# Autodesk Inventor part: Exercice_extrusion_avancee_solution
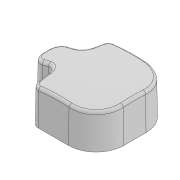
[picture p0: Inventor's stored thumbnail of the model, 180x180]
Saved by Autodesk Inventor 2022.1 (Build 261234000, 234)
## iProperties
Created: 2019-12
Part Number: Exercice_extrusion_avancee_solution
Material: Générique
Document SubType Name: Modeling
Designer: Fabian
Density: 1 g/cm^3
Appearance: Par défaut
Mass: 120.641 g
Surface Area: 860.643 cm^2
Volume: 120.641 cm^3
Author: Fabian
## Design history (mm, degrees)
sketch "Esquisse1"
  geometry: L1 (0, 70)-(0, -66.117); L2 (90, 0)-(-70, 0); L3 (90, 14.325)-(90, 0); L4 (-70, 45)-(-70, 0); L5 (44.578, 70)-(-45, 70); L6 (86.745, 24.649)-(60.961, 61.472); L7 (83, 0)-(83, 5); L8 (65, 23)-(55, 23); L9 (43, 35)-(43, 51); L10 (31, 63)-(-18, 63); L11 (-63, 18)-(-63, 0); L12 (-63, -18)-(-63, 0); L13 (0, -70)-(0, 66.117); L14 (-70, -45)-(-70, 0); L15 (31, -63)-(-18, -63); L16 (44.578, -70)-(-45, -70); L17 (43, -35)-(43, -51); L18 (90, -14.325)-(90, 0); L19 (86.745, -24.649)-(60.961, -61.472); L20 (83, 0)-(83, -5); L21 (65, -23)-(55, -23); C1 r 4 at (-60, 60); C2 r 6 at (55, 35); C3 r 4 at (-60, -60); C4 r 6 at (55, -35); A1 r 15 centre (-60, 60) between (-51, 72) and (-72, 51); A2 r 12 centre (55, 35) between (43, 35) and (55, 23); A3 r 12 centre (31, 51) between (43, 51) and (31, 63); A4 r 18 centre (72, 14.325) between (90, 14.325) and (86.745, 24.649); A5 r 20 centre (44.578, 50) between (60.961, 61.472) and (44.578, 70); A6 r 10 centre (-45, 80) between (-51, 72) and (-45, 70); A7 r 10 centre (-80, 45) between (-70, 45) and (-72, 51); A8 r 18 centre (65, 5) between (83, 5) and (65, 23); A9 r 45 centre (-18, 18) between (-18, 63) and (-63, 18); A10 r 45 centre (-18, -18) between (-63, -18) and (-18, -63); A11 r 12 centre (31, -51) between (31, -63) and (43, -51); A12 r 10 centre (-45, -80) between (-45, -70) and (-51, -72); A13 r 15 centre (-60, -60) between (-72, -51) and (-51, -72); A14 r 10 centre (-80, -45) between (-72, -51) and (-70, -45); A15 r 12 centre (55, -35) between (55, -23) and (43, -35); A16 r 20 centre (44.578, -50) between (44.578, -70) and (60.961, -61.472); A17 r 18 centre (65, -5) between (65, -23) and (83, -5); A18 r 18 centre (72, -14.325) between (86.745, -24.649) and (90, -14.325); 7 further points
  constraints: 44 end point, 40 point on circle, 32 symmetric about line, 22 centre point, 16 tangent, 14 point on line, 5 perpendicular, 4 coincident, 3 vertical, 2 horizontal, 11 other
  dimensions: "d2" = 70 distance between parallel lines of L4 L1; "d3" = 90 distance between parallel lines of L3 L1; "d5" = 30 diameter of A1; "d6" = 140 diameter of L5 L2; "d7" = 20 distance of point (90, 20) L2.start; "d8" = 35 deg angle of L3 L6; "d9" = 120 diameter of A1.centre L2; "d11" = 60 distance from line of A1.centre L1; "d12" = 8 diameter of C1; "d13" = 70 diameter of C2.centre L2; "d14" = 55 distance from line of C2.centre L1; "d15" = 12 diameter of C2; "d16" = 83 distance between parallel lines of L7 L1; "d17" = 63 distance between parallel lines of L11 L1; "d18" = 46 diameter of L8 L2 (derived); "d19" = 126 diameter of L10 L2; "d21" = 12 radius of A2; "d22" = 43 distance between parallel lines of L9 L1 (derived); "d23" = 12 radius of A3 (derived); "d24" = 18 radius of A4 (derived); "d25" = 20 radius of A5; "d26" = 10 radius of A6; "d27" = 10 radius of A7; "d28" = 18 radius of A8; "d29" = 45 radius of A9
extrude "Extrusion1" new body sketch "Esquisse1" distance "d30" = 65; taper "d31" = -1 deg
sketch "Esquisse2"
  geometry: L1 (-81.865, 65)-(61.865, 65); L2 (0, -455)-(0, 65); L3 (18, 65)-(-31, 65) reference; L4 (-55, 65)-(-65, 65) reference; A1 r 260 centre (0, -195) between (0, -455) and (0, 65); 1 further point
  constraints: 4 end point, 2 point on circle, 1 centre point, 1 collinear, 1 point on line, 1 tangent, 1 vertical, 1 vertical alignment
  dimensions: "d32" = 520 diameter of A1
revolve "Révolution1" sketch "Esquisse2" stored, may be unused: angle "d33" = 90 deg
fillet "Congé1" dims "d36" = 5
feature "Coque1" dims "d37" = 3
sketch "Esquisse3"
  geometry: L1 (-80, -5)-(-80, 5) reference; L2 (-65, 20)-(-55, 20) reference; L3 (-40, 35)-(-40, 51) reference; L4 (-31, 60)-(18, 60) reference; L5 (60, 18)-(60, -18) reference; L6 (18, -60)-(-31, -60) reference; L7 (-40, -51)-(-40, -35) reference; L8 (-55, -20)-(-65, -20) reference; L9 (-31, 63)-(18, 63) reference; L10 (-43, 35)-(-43, 51) reference; L11 (-65, 23)-(-55, 23) reference; L12 (-83, -5)-(-83, 5) reference; L13 (-55, -23)-(-65, -23) reference; L14 (-43, -51)-(-43, -35) reference; L15 (18, -63)-(-31, -63) reference; L16 (63, 18)-(63, -18) reference; L17 (18, 55)-(-31, 55); L18 (-35, 51)-(-35, 35); L19 (-55, 15)-(-65, 15); L20 (-75, 5)-(-75, -5); L21 (-65, -15)-(-55, -15); L22 (-35, -35)-(-35, -51); L23 (-31, -55)-(18, -55); L24 (55, -18)-(55, 18); L25 (-31, 56.5)-(18, 56.5); L26 (56.5, 18)-(56.5, -18); L27 (18, -56.5)-(-31, -56.5); L28 (-36.5, -51)-(-36.5, -35); L29 (-55, -16.5)-(-65, -16.5); L30 (-76.5, -5)-(-76.5, 5); L31 (-65, 16.5)-(-55, 16.5); L32 (-36.5, 35)-(-36.5, 51); A1 r 15 centre (-65, -5) between (-80, -5) and (-65, -20) reference; A2 r 15 centre (-65, 5) between (-65, 20) and (-80, 5) reference; A3 r 15 centre (-55, 35) between (-55, 20) and (-40, 35) reference; A4 r 9 centre (-31, 51) between (-31, 60) and (-40, 51) reference; A5 r 42 centre (18, 18) between (60, 18) and (18, 60) reference; A6 r 42 centre (18, -18) between (18, -60) and (60, -18) reference; A7 r 9 centre (-31, -51) between (-40, -51) and (-31, -60) reference; A8 r 15 centre (-55, -35) between (-40, -35) and (-55, -20) reference; A9 r 12 centre (-31, 51) between (-31, 63) and (-43, 51) reference; A10 r 12 centre (-55, 35) between (-55, 23) and (-43, 35) reference; A11 r 18 centre (-65, 5) between (-65, 23) and (-83, 5) reference; A12 r 18 centre (-65, -5) between (-83, -5) and (-65, -23) reference; A13 r 12 centre (-55, -35) between (-43, -35) and (-55, -23) reference; A14 r 12 centre (-31, -51) between (-43, -51) and (-31, -63) reference; A15 r 45 centre (18, -18) between (18, -63) and (63, -18) reference; A16 r 45 centre (18, 18) between (63, 18) and (18, 63) reference; A17 r 4 centre (-31, 51) between (-31, 55) and (-35, 51); A18 r 20 centre (-55, 35) between (-55, 15) and (-35, 35); A19 r 10 centre (-65, 5) between (-65, 15) and (-75, 5); A20 r 10 centre (-65, -5) between (-75, -5) and (-65, -15); A21 r 20 centre (-55, -35) between (-35, -35) and (-55, -15); A22 r 4 centre (-31, -51) between (-35, -51) and (-31, -55); A23 r 37 centre (18, -18) between (18, -55) and (55, -18); A24 r 37 centre (18, 18) between (55, 18) and (18, 55); A25 r 38.5 centre (18, 18) between (56.5, 18) and (18, 56.5); A26 r 38.5 centre (18, -18) between (18, -56.5) and (56.5, -18); A27 r 5.5 centre (-31, -51) between (-36.5, -51) and (-31, -56.5); A28 r 18.5 centre (-55, -35) between (-36.5, -35) and (-55, -16.5); A29 r 11.5 centre (-65, -5) between (-76.5, -5) and (-65, -16.5); A30 r 11.5 centre (-65, 5) between (-65, 16.5) and (-76.5, 5); A31 r 18.5 centre (-55, 35) between (-55, 16.5) and (-36.5, 35); A32 r 5.5 centre (-31, 51) between (-31, 56.5) and (-36.5, 51); 1 further point
  constraints: 32 end point, 32 point on circle, 16 centre point, 30 other
  dimensions: "d39" = 5 distance between parallel lines of L4 L17; "d40" = 1.5 distance between parallel lines of L17 L25
extrude "Extrusion3" join sketch "Esquisse3" stored distance "d41" = 10; taper "d42" = 0 deg
node "Solide1"
node "Boucle projetée1"
